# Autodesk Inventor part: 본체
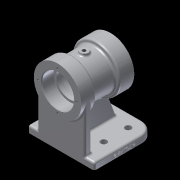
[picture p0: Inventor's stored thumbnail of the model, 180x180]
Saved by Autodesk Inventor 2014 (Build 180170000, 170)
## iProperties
Created: 2020-06
Part Number: 본체
Material: Aluminum 6061
Document SubType Name: Modeling
Designer: kh
Mass: 726.812 g
Surface Area: 640.48 cm^2
Volume: 268.196 cm^3
Density: 2.71 g/cm^3
Appearance: Aluminum - Flat
Author: kh
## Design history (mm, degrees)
sketch "Sketch1"
  geometry: L1 (24.5, 0)-(35, 0); L2 (35, 0)-(35, -22); L3 (35, -22)-(29, -22); L4 (29, -22)-(29, -56); L5 (29, -56)-(35, -56); L6 (35, -56)-(35, -78); L7 (35, -78)-(24.5, -78); L8 (0, -78)-(0, 0); L9 (23.5, -1)-(23.5, -17.7); L10 (23.2, -18)-(20, -18); L11 (20, -18)-(20, -24); L12 (20, -24)-(20, -24); L13 (23, -27)-(23, -51); L14 (20, -54)-(20, -54); L15 (20, -54)-(20, -60); L16 (20, -60)-(23.2, -60); L17 (23.5, -60.3)-(23.5, -77); L18 (23.5, -1)-(24.5, 0); L19 (23.5, -77)-(24.5, -78); A1 r 0.3 centre (23.2, -60.3) between (23.5, -60.3) and (23.2, -60); A2 r 0.3 centre (23.2, -17.7) between (23.2, -18) and (23.5, -17.7); A3 r 3 centre (20, -27) between (23, -27) and (20, -24); A4 r 3 centre (20, -51) between (20, -54) and (23, -51); 4 further points
  constraints: 38 end point, 10 parallel, 10 point on line, 8 point on circle, 8 tangent, 5 perpendicular, 4 centre point, 2 equal radius, 1 collinear, 1 horizontal
  dimensions: "d6" = 70 diameter of L2 L8; "d7" = 78 distance between parallel lines of L7 L1; "d8" = 22 distance of L5.end L6.end; "d9" = 22 distance of L1.end L2.end; "d10" = 70 diameter of L6 L8; "d11" = 58 diameter of L4 L8; "d12" = 47 diameter of L9 L8; "d13" = 47 diameter of L17 L8; "d14" = 40 diameter of L11 L8; "d15" = 40 diameter of L15 L8; "d16" = 46 diameter of L13 L8; "d17" = 18 distance between parallel lines of L1 L10; "d18" = 6 distance between parallel lines of L12 L10; "d19" = 30 distance between parallel lines of L14 L12; "d20" = 18 distance between parallel lines of L7 L16; "d21" = 1 distance of L9.start point (23.5, 0); "d22" = 45 deg angle of L9 L18; "d23" = 1 distance of L17.end point (23.5, -78) (= d21); "d24" = 45 deg angle of L17 L19 (= d22); "d25" = 0.3 radius of A1; "d26" = 3 radius of A3
revolve "Revolution1" sketch "Sketch1" stored, may be unused: angle "d27" = 90 deg
workplane "Work Plane1"
workplane "Work Plane2"
sketch "Sketch2"
  geometry: L1 (49, -5)-(-49, -5); L2 (-49, -5)-(-49, -75); L3 (-29, -95)-(29, -95); L4 (49, -75)-(49, -5); C1 r 4.5 at (29, -75); C2 r 4.5 at (29, -39); C3 r 4.5 at (-29, -75); C4 r 4.5 at (-29, -39); A1 r 20 centre (29, -75) between (29, -95) and (49, -75); A2 r 20 centre (-29, -75) between (-49, -75) and (-29, -95); 3 further points
  constraints: 8 end point, 6 centre point, 4 point on circle, 4 point on line, 4 tangent, 2 parallel, 1 equal radius, 1 horizontal, 1 perpendicular
  dimensions: "d30" = 5 distance from line of point (0, 0) L1; "d31" = 90 distance of point (49, -95) L1.start; "d32" = 98 distance of point (-49, -95) point (49, -95); "d33" = 49 distance from line of point (0, 0) L4; "d34" = 9 diameter of C1; "d35" = 70 distance from line of L1 C1.centre; "d36" = 9 diameter of C2; "d37" = 36 distance of C1.centre C2.centre; "d38" = 9 diameter of C3; "d39" = 9 diameter of C4; "d40" = 70 distance from line of L1 C3.centre; "d41" = 36 distance of C3.centre C4.centre; "d42" = 58 distance of C1.centre C3.centre; "d43" = 29 horizontal distance of point (0, 0) C2.centre; "d44" = 29 horizontal distance of point (0, 0) C1.centre; "d45" = 29 horizontal distance of point (0, 0) C4.centre; "d46" = 20 radius of A1
extrude "Extrusion1" join sketch "Sketch2" distance "d47" = 10; taper "d48" = 0 deg
fillet "Fillet1" dims "d49" = 3
sketch "Sketch3"
  geometry: L1 (-46, 5)-(46, 5) reference; L2 (-35, 5)-(35, 5); L3 (35, 5)-(35, 15); L4 (35, 15)-(-35, 15); L5 (-35, 15)-(-35, 5); 1 further point
  constraints: 8 end point, 2 parallel, 1 horizontal, 1 perpendicular, 1 point on line
  dimensions: "d50" = 70 distance between parallel lines of L3 L5; "d51" = 35 distance from line of point (0, 0) L5; "d52" = 10 distance between parallel lines of L2 L4
extrude "Extrusion2" join sketch "Sketch3" stored distance "d53" = 10; taper "d54" = 0 deg
sketch "Sketch4"
  geometry: L1 (-28.008, -66.671)-(-72.872, -83); L2 (-72.872, -83)-(-72.872, -13.378); L3 (-72.872, -13.378)-(-28.008, -13.378); L4 (-28.008, -13.378)-(-28.008, -66.671); L5 (-80, -95)-(-73, -95) reference; 1 further point
  constraints: 8 end point, 2 perpendicular, 1 vertical
  dimensions: "d55" = 70 deg angle of L2 L1; "d56" = 12 distance from line of L5 L1.end
extrude "Extrusion3" join sketch "Sketch4" stored distance "d57" = 10; taper "d58" = 0 deg
workplane "Work Plane3"
sketch "Sketch5"
  geometry: L1 (-35, 0)-(35, 0) reference; C1 r 6 at (0, -39); 2 further points
  constraints: 1 centre point, 1 midpoint, 1 vertical alignment
  dimensions: "d60" = 12 diameter of C1; "d61" = 39 distance from line of L1 C1.centre
extrude "Extrusion4" join sketch "Sketch5" stored distance "d62" = 3; taper "d63" = 0 deg
hole "Hole1" diameter "d66" = 5.188; stored, may be unused: countersink angle "d70" = 90 deg, drill point angle "d72" = 118 deg; dims "d64" = 10, "d65" = 10, "d67" = 15, "d68" = 4, "d69" = 2, "d71" = 15
fillet "Fillet2" dims "d73" = 3
fillet "Fillet3" dims "d74" = 3
sketch "Sketch6"
  geometry: L1 (-67, 0)-(0, 0) reference; L2 (-70, 7)-(-70, 0) reference; 2 further points
  constraints: 1 other
  dimensions: "d75" = 45 distance from line of L2 point (-25, 4); "d76" = 4 distance from line of L1 point (-25, 4)
emboss "Emboss1" sketch "Sketch6" dims "d77" = 0.5, "d78" = 0
sketch "Sketch7" dims "d79" = 57
  geometry: C1 r 35 at (0, 0) reference; 2 further points
  constraints: 2 vertical alignment, 1 coincident, 2 other
hole "Hole2" sketch "Sketch7" at (0, 28.5) diameter "d80" = 3.242; stored, may be unused: countersink angle "d84" = 90 deg, drill point angle "d86" = 118 deg; dims "d81" = 10, "d82" = 4, "d83" = 2, "d85" = 12
pattern_circular "Circular Pattern1" dims angle "d88" = 360 deg
sketch "Sketch8" dims "d90" = 57
  geometry: C1 r 24.5 at (0, 0) reference; 2 further points
  constraints: 2 vertical alignment, 1 coincident, 2 other
hole "Hole3" sketch "Sketch8" at (0, 28.5) diameter "d91" = 3.242; stored, may be unused: countersink angle "d95" = 90 deg, drill point angle "d97" = 118 deg; dims "d92" = 10, "d93" = 4, "d94" = 2, "d96" = 12
pattern_circular "Circular Pattern2" dims angle "d99" = 360 deg
body "Solid1"
other parameters: "d29" = -5, "d59" = 32
